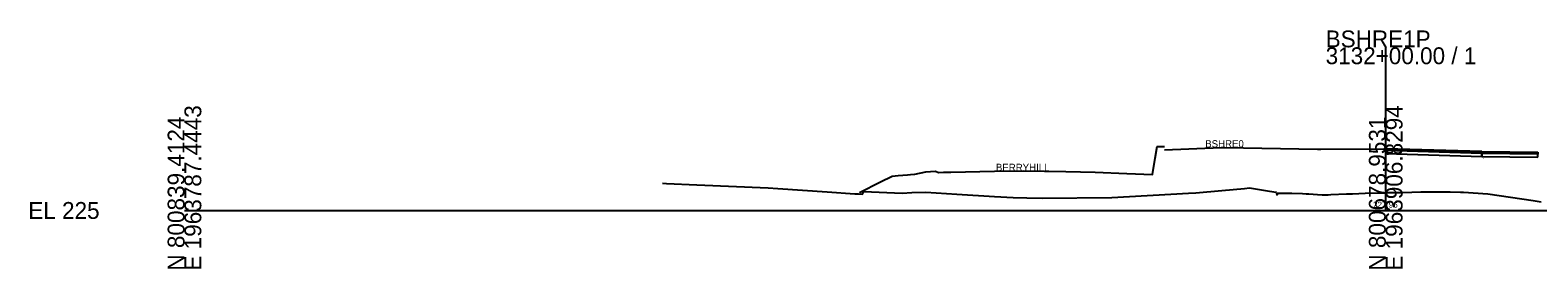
# Model space of a CAD drawing. Extents: x -26 to 403, y -10 to 6039.
# Drawn here: x -25.7 to 225.3, y 3490.3 to 3530 of the extents above; entities that cross this region are included whole.
import ezdxf

# ---------------------------------------------------------------- set-up
doc = ezdxf.new("R2010")
doc.units = 0
for name, color, linetype in [('Default', 7, 'Continuous'), ('RD_GPK_XS_Cell', 7, 'Continuous'), ('RD_TX_Misc1', 7, 'Continuous'), ('RD_XS_Base', 7, 'Continuous'), ('RD_XS_ExGround', 7, 'Continuous'), ('RD_XS_Pave', 7, 'Continuous'), ('RD_XS_PaveOvlay', 7, 'Continuous'), ('RD_XS_TX_Elev_EX', 7, 'Continuous')]:
    doc.layers.add(name, color=color, linetype=linetype)

msp = doc.modelspace()

# ---------------------------------------------------------------- linework, layer by layer
at = {"layer": 'RD_GPK_XS_Cell'}
for p, q in [((200, 3500), (200, 3527.11)), ((0, 3500), (200, 3500)), ((200, 3500), (400, 3500))]:
    msp.add_line(p, q, dxfattribs=at)
at = {"layer": 'RD_XS_Base'}
for points in [[(216, 3509.46), (200, 3509.94)], [(200, 3509.94), (200, 3509.44)], [(200, 3509.44), (216, 3508.96)], [(216, 3509.46), (216, 3508.96)], [(225.33, 3509.38), (216, 3509.46)], [(216, 3508.96), (216, 3509.46)], [(225.33, 3508.88), (225.33, 3509.38)], [(216, 3508.96), (225.33, 3508.88)]]:
    msp.add_lwpolyline(points, dxfattribs=at)
at = {"layer": 'RD_XS_ExGround'}
msp.add_lwpolyline([(79.58, 3504.51), (80.26, 3504.49), (85.3, 3504.27), (97.2, 3503.76), (98.81, 3503.66), (107.03, 3503.1), (111.6, 3502.79), (112.2, 3502.77), (112.91, 3502.72), (113.09, 3503.17), (119.51, 3502.88), (121.12, 3502.96), (123.43, 3503.03), (125.16, 3502.95), (128.58, 3502.7), (134.87, 3502.31), (137.97, 3502.16), (140.22, 3502.12), (142.82, 3502.07), (154.41, 3502.18), (167.14, 3502.85), (168.38, 3502.92), (172.74, 3503.3), (176.48, 3503.65), (177.31, 3503.75), (180.67, 3503.23), (181.77, 3503.06), (181.89, 3502.61), (182.08, 3502.88), (183.01, 3502.88), (184.35, 3502.87), (186.15, 3502.82), (186.75, 3502.79), (187.2, 3502.75), (188.65, 3502.63), (189.44, 3502.58), (190.39, 3502.62), (190.85, 3502.64), (193.47, 3502.74), (193.89, 3502.76), (194.45, 3502.78), (196.57, 3502.85), (198.64, 3502.92), (199.66, 3502.95), (200, 3502.96), (202.84, 3503.01), (205.85, 3503.07), (207.04, 3503.08), (208.17, 3503.1), (208.98, 3503.11), (210.24, 3503.11), (210.71, 3503.11), (212.45, 3503.06), (212.93, 3503.05), (216.99, 3502.79), (224.57, 3501.64), (225.86, 3501.45)], dxfattribs=at)
at = {"layer": 'RD_XS_Pave'}
for points in [[(112.36, 3502.97), (115.91, 3504.75), (117.84, 3505.71), (118.81, 3505.79), (120.37, 3505.91), (120.86, 3505.95), (121.59, 3506.01), (123.43, 3506.41), (124.99, 3506.54), (125.6, 3506.33), (126.38, 3506.34), (127.6, 3506.37), (134.84, 3506.51), (139.61, 3506.6), (146.75, 3506.46), (151.61, 3506.36), (156.91, 3506.15), (161.18, 3505.98), (161.62, 3508.71), (161.93, 3510.65), (162.67, 3510.65), (163.19, 3510.65)], [(163.17, 3510.06), (172.61, 3510.45), (173.19, 3510.47), (188.62, 3510.18), (189.22, 3510.17), (199.69, 3510.25), (200.02, 3510.25)], [(200, 3509.94), (200, 3510.1)], [(200, 3510.1), (216, 3509.62)], [(216, 3509.46), (200, 3509.94)], [(216, 3509.62), (216, 3509.46)], [(216, 3509.62), (225.33, 3509.55)], [(216, 3509.46), (216, 3509.62)], [(225.33, 3509.38), (216, 3509.46)], [(225.33, 3509.55), (225.33, 3509.38)]]:
    msp.add_lwpolyline(points, dxfattribs=at)
at = {"layer": 'RD_XS_PaveOvlay'}
for points in [[(216, 3509.78), (200, 3510.26)], [(200, 3510.26), (200, 3510.1)], [(200, 3510.1), (216, 3509.62)], [(216, 3509.62), (216, 3509.78)], [(216, 3509.78), (225.33, 3509.71)], [(216, 3509.62), (216, 3509.78)], [(225.33, 3509.55), (216, 3509.62)], [(225.33, 3509.71), (225.33, 3509.55)]]:
    msp.add_lwpolyline(points, dxfattribs=at)

# ---------------------------------------------------------------- texts
at = {"layer": 'Default'}
for s, height, p in [('CL', 0.208, (200, 3510.05)), ('CL1', 0.208, (200, 3509.89)), ('CL2', 0.208, (200, 3509.73)), ('CL3', 0.208, (200, 3509.23)), ('Exterior Boundary', 0.2083, (200, 3510.05)), ('R_EP', 0.208, (216, 3509.57)), ('R_EP1', 0.208, (216, 3509.41)), ('R_EP2', 0.208, (216, 3509.25)), ('R_EP3', 0.208, (216, 3508.75)), ('-', 0.0001, (0, 3500))]:
    msp.add_text(s, height=height, dxfattribs=at).set_placement(p)
at = {"layer": 'RD_GPK_XS_Cell'}
for s, p in [('BSHRE1P', (190, 3527.11)), ('3132+00.00 / 1', (190, 3524.31)), ('EL 225', (-26, 3498.6))]:
    msp.add_text(s, height=2.8, dxfattribs=at).set_placement(p)
for s, p in [('E 1963787.4443', (2.8, 3490)), ('E 1963906.8294', (202.8, 3490)), ('N 800839.4124', (0, 3490)), ('N 800678.9531', (200, 3490))]:
    msp.add_text(s, height=2.8, rotation=90, dxfattribs=at).set_placement(p)
at = {"layer": 'RD_TX_Misc1'}
for s, p in [('BSHRE0', (169.95, 3510.48)), ('BERRYHILL', (135.1, 3506.56))]:
    msp.add_text(s, height=1.2, dxfattribs=at).set_placement(p)
at = {"layer": 'RD_XS_TX_Elev_EX'}
msp.add_text('227.96', height=1, dxfattribs=at).set_placement((197.9, 3500.46))

doc.saveas('drawing.dxf')
